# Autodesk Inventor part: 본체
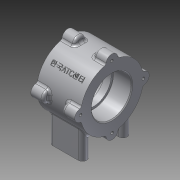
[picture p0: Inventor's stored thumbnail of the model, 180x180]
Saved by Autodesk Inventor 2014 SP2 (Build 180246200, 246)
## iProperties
Created: 2015-03
Part Number: 본체
Material: 알루미늄 6061
Document SubType Name: Modeling
Designer: 201-06
Mass: 450.777 g
Surface Area: 332.694 cm^2
Volume: 166.338 cm^3
Density: 2.71 g/cm^3
Appearance: 알루미늄 - 평지
Author: 201-06
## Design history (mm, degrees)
sketch "스케치1"
  geometry: C1 r 37 at (0, 0); 1 further point
  constraints: 1 centre point, 1 coincident
  dimensions: "d0" = 74 diameter of C1
extrude "돌출1" new body sketch "스케치1" distance "d1" = 52; taper "d2" = 0 deg
sketch "스케치2"
  geometry: L1 (-37, -7.148)-(-36.303, -7.148); L2 (-37, 6.852)-(-36.36, 6.852); A1 r 37 centre (0, 0) between (-37, -0.148) and (-36.303, -7.148) reference; A2 r 7 centre (-37, -0.148) between (-37, 6.852) and (-37, -7.148); 1 further point
  constraints: 5 point on circle, 4 end point, 2 tangent, 1 centre point, 1 horizontal, 1 parallel, 2 other
  dimensions: "d3" = 14 diameter of A2; "d4" = 6.852 distance from line of point (0, 0) L2
extrude "돌출2" join sketch "스케치2" distance "d5" = 15; taper "d6" = 0 deg
fillet "모깎기1" dims "d7" = 3
fillet "모깎기2" dims "d8" = 3
node "작업 평면1"
sketch "스케치4"
  geometry: L1 (19, -56)-(29, -56); L2 (19, -56)-(19, -20.462); L3 (19, -20.462)-(29, -14.665); L4 (29, -14.665)-(29, -56); 1 further point
  constraints: 8 end point, 1 horizontal, 1 parallel, 1 perpendicular
  dimensions: "d20" = 10 distance of L1.start L1.end; "d21" = 56 distance from line of L1 point (0, 0); "d22" = 19 horizontal distance of L1.start point (0, 0); "d23" = 59.8977 deg angle of L3 L4; "d24" = 27.23161 distance from line of point (0, 0) L3
extrude "돌출3" join sketch "스케치4" stored distance "d25" = 40; taper "d26" = 0 deg
fillet "모깎기3" dims "d27" = 5
fillet "모깎기4" dims "d28" = 3
node "작업 평면5"
sketch "스케치5"
  geometry: L1 (0, -48)-(30, -48) reference; L2 (30, -58)-(0, -58) reference; A1 r 5 centre (30, -5) between (30, -10) and (30, 0) reference; A2 r 5 centre (0, -5) between (0, 0) and (0, -10) reference; A3 r 5 centre (30, -53) between (30, -58) and (30, -48) reference; A4 r 5 centre (0, -53) between (0, -48) and (0, -58) reference; 5 further points
  constraints: 4 coincident
hole "구멍1" sketch "스케치5" at (0, -5), (30, -5), (30, -53), (0, -53) diameter "d30" = 4.134; stored, may be unused: countersink angle "d34" = 90 deg, drill point angle "d36" = 118 deg; dims "d31" = 6, "d32" = 4, "d33" = 2, "d35" = 8
sketch "스케치6"
  geometry: C1 r 23.5 at (0, 0); A1 r 37 centre (0, 0) between (-9.247, 35.826) and (-35.899, 8.96) reference
  constraints: 1 centre point, 1 coincident
  dimensions: "d37" = 47 diameter of C1
extrude "돌출4" cut sketch "스케치6" distance "d38" = 22; taper "d39" = 0 deg
sketch "스케치7"
  geometry: C1 r 23.5 at (0, 0); A1 r 37 centre (0, 0) between (8.96, -35.899) and (35.826, -9.247) reference
  constraints: 1 centre point, 1 coincident
  dimensions: "d40" = 47 diameter of C1
extrude "돌출5" cut sketch "스케치7" distance "d41" = 22; taper "d42" = 0 deg
sketch "스케치8"
  geometry: C1 r 23.5 at (0, 0) reference; C2 r 21 at (0, 0)
  constraints: 1 centre point, 1 coincident
  dimensions: "d43" = 42 diameter of C2
extrude "돌출6" cut sketch "스케치8" stored distance "d44" = 22; taper "d45" = 0 deg
sketch "스케치9"
  geometry: A1 r 7 centre (0.148, -37) between (-6.736, -38.266) and (7.042, -38.211) reference; A2 r 7 centre (37, 0.148) between (38.266, -6.736) and (38.211, 7.042) reference; A3 r 7 centre (-0.148, 37) between (6.736, 38.266) and (-7.042, 38.211) reference; A4 r 7 centre (-37, -0.148) between (-38.266, 6.736) and (-38.211, -7.042) reference; 4 further points
  constraints: 4 coincident
hole "구멍2" sketch "스케치9" at (-37, -0.148), (0.148, -37), (37, 0.148), (-0.148, 37) diameter "d46" = 3.242; stored, may be unused: countersink angle "d50" = 90 deg, drill point angle "d52" = 118 deg; dims "d47" = 8, "d48" = 4, "d49" = 2, "d51" = 11
sketch "스케치10"
  geometry: C1 r 1.621 at (-37, 0.148) reference; A1 r 7 centre (0.148, 37) between (7.042, 38.211) and (-6.736, 38.266) reference; A2 r 7 centre (-0.148, -37) between (-7.042, -38.211) and (6.736, -38.266) reference; A3 r 7 centre (37, -0.148) between (38.211, -7.042) and (38.266, 6.736) reference; 4 further points
  constraints: 4 coincident
hole "구멍3" sketch "스케치10" at (-37, 0.148), (0.148, 37), (37, -0.148), (-0.148, -37) diameter "d53" = 3.242; stored, may be unused: countersink angle "d57" = 90 deg, drill point angle "d59" = 118 deg; dims "d54" = 8, "d55" = 4, "d56" = 2, "d58" = 11
node "작업 평면7"
  node "작업 평면6"
sketch "스케치11"
  geometry: L1 (0, 3.246)-(0, 41.088) reference; 2 further points
  constraints: 1 horizontal alignment, 1 other
  dimensions: "d62" = 26 distance from line of L1 point (-26, 22.04)
feature "엠보싱1" sketch "스케치11" dims "d63" = 0.5, "d64" = 0
chamfer "모따기1" distance "d65" = 1; stored, may be unused: second distance "d66" = 2, angle "d67" = 45 deg
fillet "모깎기5" dims "d68" = 0.3
node "솔리드1"
pattern_circular "원형 패턴1" dims "d10" = 360 deg
mirror "대칭1"
mirror "대칭2"
node "투영된 루프2"
other parameters: "d12" = 26, "d29" = 0, "d60" = 45 deg, "d61" = 56.75
